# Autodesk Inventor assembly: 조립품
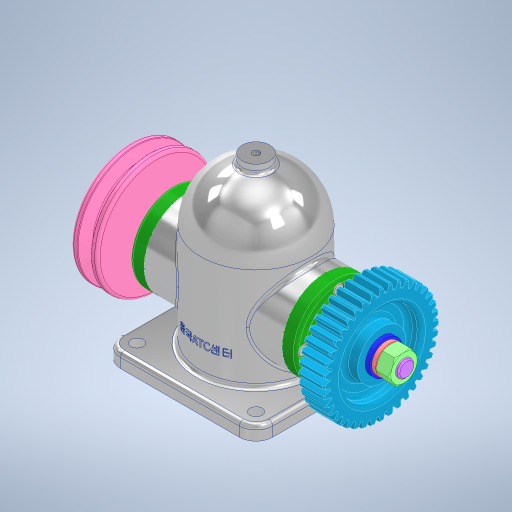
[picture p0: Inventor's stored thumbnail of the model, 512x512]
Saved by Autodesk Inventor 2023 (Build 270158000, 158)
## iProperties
Created: 2025-04
Part Number: 조립품
Document SubType Name: Assembly
Designer: Admin
Author: Admin
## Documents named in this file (14)
- C:\Users\Admin\Desktop\750406V1005\조립품.iam
- C:\Users\Admin\Desktop\750406V1005\본체.ipt
- C:\Users\Admin\Desktop\750406V1005\깊은 홈 볼 베어링 6203.ipt
- C:\Users\Admin\Desktop\750406V1005\축.ipt
- C:\Users\Admin\Desktop\750406V1005\커버.ipt
- C:\Users\Admin\Desktop\750406V1005\오일 실 26 38 8.ipt
- C:\Users\Admin\Desktop\750406V1005\6각 구멍붙이 볼트 M4x12.ipt
- C:\Users\Admin\Desktop\750406V1005\칼라.ipt
- C:\Users\Admin\Desktop\750406V1005\평행 키 5x5x12.ipt
- C:\Users\Admin\Desktop\750406V1005\스퍼기어.ipt
- C:\Users\Admin\Desktop\750406V1005\V 벨트 풀리.ipt
- C:\Users\Admin\Desktop\750406V1005\평와셔 M12.ipt
- C:\Users\Admin\Desktop\750406V1005\스프링 와셔 M12.ipt
- C:\Users\Admin\Desktop\750406V1005\6각 너트 M12x1.ipt
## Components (11 placed, 3 different names)
1. 6각 구멍붙이 볼트 M4x12:1
2. 6각 구멍붙이 볼트 M4x12:2
3. 6각 구멍붙이 볼트 M4x12:3
4. 6각 구멍붙이 볼트 M4x12:4
5. 6각 구멍붙이 볼트 M4x12:5
6. 6각 구멍붙이 볼트 M4x12:6
7. 6각 구멍붙이 볼트 M4x12:7
8. 6각 구멍붙이 볼트 M4x12:8
9. V 벨트 풀리:1
10. 6각 너트 M12x1:1
11. 6각 너트 M12x1:2
